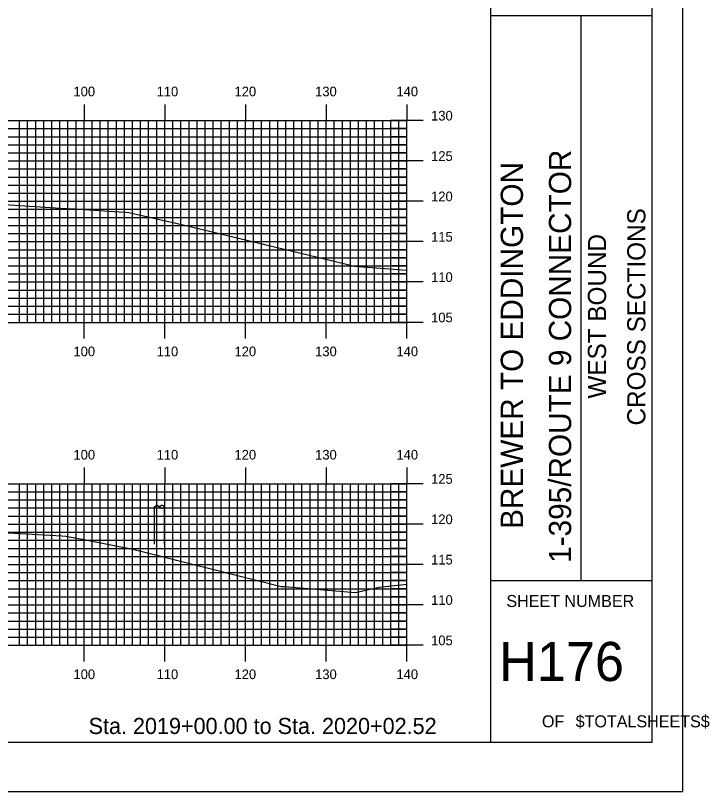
# Model space of a CAD drawing. Extents: x 855468 to 855811, y 366605 to 366825.
# Drawn here: x 855725.1 to 855811.1, y 366604.9 to 366701.1 of the extents above; entities that cross this region are included whole.
import ezdxf

# ---------------------------------------------------------------- set-up
doc = ezdxf.new("R2010")
doc.units = 0
for name, color, linetype in [('BORDER', 7, 'Continuous'), ('H_V ANNOTATION', 7, 'Continuous'), ('MAJOR', 7, 'Continuous'), ('MINOR', 7, 'Continuous'), ('PLOT BOUNDARY', 7, 'Continuous'), ('S_Roadway_Centerline', 7, 'Continuous'), ('S_Utilities_Pole_StreetLight', 7, 'Continuous')]:
    doc.layers.add(name, color=color, linetype=linetype)

msp = doc.modelspace()

# ---------------------------------------------------------------- linework, layer by layer
at = {"layer": 'BORDER'}
for p, q in [((855783.982, 366611.055), (855783.982, 366821.055)), ((855783.982, 366701.061), (855803.982, 366701.061)), ((855795.164, 366631.061), (855795.164, 366701.061)), ((855783.982, 366631.061), (855803.982, 366631.061))]:
    msp.add_line(p, q, dxfattribs=at)
msp.add_lwpolyline([(855483.982, 366611.055), (855803.982, 366611.055), (855803.982, 366821.055), (855483.982, 366821.055)], close=True, dxfattribs=at)
at = {"layer": 'MAJOR'}
for p, q in [((855733.582, 366690.059), (855733.582, 366688.055)), ((855743.582, 366690.059), (855743.582, 366688.055)), ((855753.582, 366690.059), (855753.582, 366688.055)), ((855763.582, 366690.059), (855763.582, 366688.055)), ((855773.582, 366690.059), (855773.582, 366688.055)), ((855493.582, 366688.055), (855773.582, 366688.055)), ((855493.582, 366688.055), (855773.582, 366688.055)), ((855733.582, 366663.055), (855733.582, 366688.055)), ((855743.582, 366663.055), (855743.582, 366688.055)), ((855753.582, 366663.055), (855753.582, 366688.055)), ((855763.582, 366663.055), (855763.582, 366688.055)), ((855775.586, 366688.055), (855771.578, 366688.055)), ((855773.582, 366663.055), (855773.582, 366688.055)), ((855773.582, 366663.055), (855773.582, 366688.055)), ((855493.582, 366683.055), (855773.582, 366683.055)), ((855775.586, 366683.055), (855771.578, 366683.055)), ((855493.582, 366678.055), (855773.582, 366678.055)), ((855775.586, 366678.055), (855771.578, 366678.055)), ((855493.582, 366673.055), (855773.582, 366673.055)), ((855775.586, 366673.055), (855771.578, 366673.055)), ((855493.582, 366668.055), (855773.582, 366668.055)), ((855775.586, 366668.055), (855771.578, 366668.055)), ((855493.582, 366663.055), (855773.582, 366663.055)), ((855493.582, 366663.055), (855773.582, 366663.055)), ((855733.582, 366661.051), (855733.582, 366663.055)), ((855743.582, 366661.051), (855743.582, 366663.055)), ((855753.582, 366661.051), (855753.582, 366663.055)), ((855763.582, 366661.051), (855763.582, 366663.055)), ((855775.586, 366663.055), (855771.578, 366663.055)), ((855773.582, 366661.051), (855773.582, 366663.055)), ((855733.582, 366645.059), (855733.582, 366643.055)), ((855743.582, 366645.059), (855743.582, 366643.055)), ((855753.582, 366645.059), (855753.582, 366643.055)), ((855763.582, 366645.059), (855763.582, 366643.055)), ((855773.582, 366645.059), (855773.582, 366643.055)), ((855493.582, 366643.055), (855773.582, 366643.055)), ((855493.582, 366643.055), (855773.582, 366643.055)), ((855733.582, 366623.055), (855733.582, 366643.055)), ((855743.582, 366623.055), (855743.582, 366643.055)), ((855753.582, 366623.055), (855753.582, 366643.055)), ((855763.582, 366623.055), (855763.582, 366643.055)), ((855775.586, 366643.055), (855771.578, 366643.055)), ((855773.582, 366623.055), (855773.582, 366643.055)), ((855773.582, 366623.055), (855773.582, 366643.055)), ((855493.582, 366638.055), (855773.582, 366638.055)), ((855775.586, 366638.055), (855771.578, 366638.055)), ((855493.582, 366633.055), (855773.582, 366633.055)), ((855775.586, 366633.055), (855771.578, 366633.055)), ((855493.582, 366628.055), (855773.582, 366628.055)), ((855775.586, 366628.055), (855771.578, 366628.055)), ((855493.582, 366623.055), (855773.582, 366623.055)), ((855493.582, 366623.055), (855773.582, 366623.055)), ((855733.582, 366621.051), (855733.582, 366623.055)), ((855743.582, 366621.051), (855743.582, 366623.055)), ((855753.582, 366621.051), (855753.582, 366623.055)), ((855763.582, 366621.051), (855763.582, 366623.055)), ((855775.586, 366623.055), (855771.578, 366623.055)), ((855773.582, 366621.051), (855773.582, 366623.055))]:
    msp.add_line(p, q, dxfattribs=at)
at = {"layer": 'MINOR'}
for p, q in [((855725.582, 366663.055), (855725.582, 366688.055)), ((855726.582, 366663.055), (855726.582, 366688.055)), ((855727.582, 366663.055), (855727.582, 366688.055)), ((855728.582, 366663.055), (855728.582, 366688.055)), ((855729.582, 366663.055), (855729.582, 366688.055)), ((855730.582, 366663.055), (855730.582, 366688.055)), ((855731.582, 366663.055), (855731.582, 366688.055)), ((855732.582, 366663.055), (855732.582, 366688.055)), ((855734.582, 366663.055), (855734.582, 366688.055)), ((855735.582, 366663.055), (855735.582, 366688.055)), ((855736.582, 366663.055), (855736.582, 366688.055)), ((855737.582, 366663.055), (855737.582, 366688.055)), ((855738.582, 366663.055), (855738.582, 366688.055)), ((855739.582, 366663.055), (855739.582, 366688.055)), ((855740.582, 366663.055), (855740.582, 366688.055)), ((855741.582, 366663.055), (855741.582, 366688.055)), ((855742.582, 366663.055), (855742.582, 366688.055)), ((855744.582, 366663.055), (855744.582, 366688.055)), ((855745.582, 366663.055), (855745.582, 366688.055)), ((855746.582, 366663.055), (855746.582, 366688.055)), ((855747.582, 366663.055), (855747.582, 366688.055)), ((855748.582, 366663.055), (855748.582, 366688.055)), ((855749.582, 366663.055), (855749.582, 366688.055)), ((855750.582, 366663.055), (855750.582, 366688.055)), ((855751.582, 366663.055), (855751.582, 366688.055)), ((855752.582, 366663.055), (855752.582, 366688.055)), ((855754.582, 366663.055), (855754.582, 366688.055)), ((855755.582, 366663.055), (855755.582, 366688.055)), ((855756.582, 366663.055), (855756.582, 366688.055)), ((855757.582, 366663.055), (855757.582, 366688.055)), ((855758.582, 366663.055), (855758.582, 366688.055)), ((855759.582, 366663.055), (855759.582, 366688.055)), ((855760.582, 366663.055), (855760.582, 366688.055)), ((855761.582, 366663.055), (855761.582, 366688.055)), ((855762.582, 366663.055), (855762.582, 366688.055)), ((855764.582, 366663.055), (855764.582, 366688.055)), ((855765.582, 366663.055), (855765.582, 366688.055)), ((855766.582, 366663.055), (855766.582, 366688.055)), ((855767.582, 366663.055), (855767.582, 366688.055)), ((855768.582, 366663.055), (855768.582, 366688.055)), ((855769.582, 366663.055), (855769.582, 366688.055)), ((855770.582, 366663.055), (855770.582, 366688.055)), ((855771.582, 366663.055), (855771.582, 366688.055)), ((855772.582, 366663.055), (855772.582, 366688.055)), ((855493.582, 366687.055), (855773.582, 366687.055)), ((855773.582, 366687.055), (855771.578, 366687.055)), ((855493.582, 366686.055), (855773.582, 366686.055)), ((855773.582, 366686.055), (855771.578, 366686.055)), ((855493.582, 366685.055), (855773.582, 366685.055)), ((855773.582, 366685.055), (855771.578, 366685.055)), ((855493.582, 366684.055), (855773.582, 366684.055)), ((855773.582, 366684.055), (855771.578, 366684.055)), ((855493.582, 366682.055), (855773.582, 366682.055)), ((855773.582, 366682.055), (855771.578, 366682.055)), ((855493.582, 366681.055), (855773.582, 366681.055)), ((855773.582, 366681.055), (855771.578, 366681.055)), ((855493.582, 366680.055), (855773.582, 366680.055)), ((855773.582, 366680.055), (855771.578, 366680.055)), ((855493.582, 366679.055), (855773.582, 366679.055)), ((855773.582, 366679.055), (855771.578, 366679.055)), ((855493.582, 366677.055), (855773.582, 366677.055)), ((855773.582, 366677.055), (855771.578, 366677.055)), ((855493.582, 366676.055), (855773.582, 366676.055)), ((855773.582, 366676.055), (855771.578, 366676.055)), ((855493.582, 366675.055), (855773.582, 366675.055)), ((855773.582, 366675.055), (855771.578, 366675.055)), ((855493.582, 366674.055), (855773.582, 366674.055)), ((855773.582, 366674.055), (855771.578, 366674.055)), ((855493.582, 366672.055), (855773.582, 366672.055)), ((855773.582, 366672.055), (855771.578, 366672.055)), ((855493.582, 366671.055), (855773.582, 366671.055)), ((855773.582, 366671.055), (855771.578, 366671.055)), ((855493.582, 366670.055), (855773.582, 366670.055)), ((855773.582, 366670.055), (855771.578, 366670.055)), ((855493.582, 366669.055), (855773.582, 366669.055)), ((855773.582, 366669.055), (855771.578, 366669.055)), ((855493.582, 366667.055), (855773.582, 366667.055)), ((855773.582, 366667.055), (855771.578, 366667.055)), ((855493.582, 366666.055), (855773.582, 366666.055)), ((855773.582, 366666.055), (855771.578, 366666.055)), ((855493.582, 366665.055), (855773.582, 366665.055)), ((855773.582, 366665.055), (855771.578, 366665.055)), ((855493.582, 366664.055), (855773.582, 366664.055)), ((855773.582, 366664.055), (855771.578, 366664.055)), ((855725.582, 366623.055), (855725.582, 366643.055)), ((855726.582, 366623.055), (855726.582, 366643.055)), ((855727.582, 366623.055), (855727.582, 366643.055)), ((855728.582, 366623.055), (855728.582, 366643.055)), ((855729.582, 366623.055), (855729.582, 366643.055)), ((855730.582, 366623.055), (855730.582, 366643.055)), ((855731.582, 366623.055), (855731.582, 366643.055)), ((855732.582, 366623.055), (855732.582, 366643.055)), ((855734.582, 366623.055), (855734.582, 366643.055)), ((855735.582, 366623.055), (855735.582, 366643.055)), ((855736.582, 366623.055), (855736.582, 366643.055)), ((855737.582, 366623.055), (855737.582, 366643.055)), ((855738.582, 366623.055), (855738.582, 366643.055)), ((855739.582, 366623.055), (855739.582, 366643.055)), ((855740.582, 366623.055), (855740.582, 366643.055)), ((855741.582, 366623.055), (855741.582, 366643.055)), ((855742.582, 366623.055), (855742.582, 366643.055)), ((855744.582, 366623.055), (855744.582, 366643.055)), ((855745.582, 366623.055), (855745.582, 366643.055)), ((855746.582, 366623.055), (855746.582, 366643.055)), ((855747.582, 366623.055), (855747.582, 366643.055)), ((855748.582, 366623.055), (855748.582, 366643.055)), ((855749.582, 366623.055), (855749.582, 366643.055)), ((855750.582, 366623.055), (855750.582, 366643.055)), ((855751.582, 366623.055), (855751.582, 366643.055)), ((855752.582, 366623.055), (855752.582, 366643.055)), ((855754.582, 366623.055), (855754.582, 366643.055)), ((855755.582, 366623.055), (855755.582, 366643.055)), ((855756.582, 366623.055), (855756.582, 366643.055)), ((855757.582, 366623.055), (855757.582, 366643.055)), ((855758.582, 366623.055), (855758.582, 366643.055)), ((855759.582, 366623.055), (855759.582, 366643.055)), ((855760.582, 366623.055), (855760.582, 366643.055)), ((855761.582, 366623.055), (855761.582, 366643.055)), ((855762.582, 366623.055), (855762.582, 366643.055)), ((855764.582, 366623.055), (855764.582, 366643.055)), ((855765.582, 366623.055), (855765.582, 366643.055)), ((855766.582, 366623.055), (855766.582, 366643.055)), ((855767.582, 366623.055), (855767.582, 366643.055)), ((855768.582, 366623.055), (855768.582, 366643.055)), ((855769.582, 366623.055), (855769.582, 366643.055)), ((855770.582, 366623.055), (855770.582, 366643.055)), ((855771.582, 366623.055), (855771.582, 366643.055)), ((855772.582, 366623.055), (855772.582, 366643.055)), ((855493.582, 366642.055), (855773.582, 366642.055)), ((855773.582, 366642.055), (855771.578, 366642.055)), ((855493.582, 366641.055), (855773.582, 366641.055)), ((855773.582, 366641.055), (855771.578, 366641.055)), ((855493.582, 366640.055), (855773.582, 366640.055)), ((855773.582, 366640.055), (855771.578, 366640.055)), ((855493.582, 366639.055), (855773.582, 366639.055)), ((855773.582, 366639.055), (855771.578, 366639.055)), ((855493.582, 366637.055), (855773.582, 366637.055)), ((855773.582, 366637.055), (855771.578, 366637.055)), ((855493.582, 366636.055), (855773.582, 366636.055)), ((855773.582, 366636.055), (855771.578, 366636.055)), ((855493.582, 366635.055), (855773.582, 366635.055)), ((855773.582, 366635.055), (855771.578, 366635.055)), ((855493.582, 366634.055), (855773.582, 366634.055)), ((855773.582, 366634.055), (855771.578, 366634.055)), ((855493.582, 366632.055), (855773.582, 366632.055)), ((855773.582, 366632.055), (855771.578, 366632.055)), ((855493.582, 366631.055), (855773.582, 366631.055)), ((855773.582, 366631.055), (855771.578, 366631.055)), ((855493.582, 366630.055), (855773.582, 366630.055)), ((855773.582, 366630.055), (855771.578, 366630.055)), ((855493.582, 366629.055), (855773.582, 366629.055)), ((855773.582, 366629.055), (855771.578, 366629.055)), ((855493.582, 366627.055), (855773.582, 366627.055)), ((855773.582, 366627.055), (855771.578, 366627.055)), ((855493.582, 366626.055), (855773.582, 366626.055)), ((855773.582, 366626.055), (855771.578, 366626.055)), ((855493.582, 366625.055), (855773.582, 366625.055)), ((855773.582, 366625.055), (855771.578, 366625.055)), ((855493.582, 366624.055), (855773.582, 366624.055)), ((855773.582, 366624.055), (855771.578, 366624.055))]:
    msp.add_line(p, q, dxfattribs=at)
at = {"layer": 'PLOT BOUNDARY'}
msp.add_lwpolyline([(855467.796, 366604.937), (855807.796, 366604.937), (855807.796, 366824.937), (855467.796, 366824.937)], close=True, dxfattribs=at)
at = {"layer": 'S_Roadway_Centerline'}
for points in [[(855723.706, 366677.657), (855730.643, 366677.215), (855732.433, 366677.101), (855739.144, 366676.679), (855745.851, 366675.147), (855756.145, 366672.657), (855764.581, 366670.652), (855767.084, 366670.023), (855773.582, 366669.525)], [(855724.168, 366636.967), (855730.829, 366636.613), (855731.3, 366636.583), (855733.534, 366636.139), (855739.617, 366634.963), (855754.723, 366631.14), (855758.013, 366630.332), (855758.398, 366630.326), (855767.211, 366629.579), (855770.165, 366630.236), (855773.582, 366630.615)]]:
    msp.add_lwpolyline(points, dxfattribs=at)
at = {"layer": 'S_Utilities_Pole_StreetLight'}
for p, q in [((855742.296, 366635.581), (855742.293, 366640.2)), ((855742.296, 366640.2), (855742.452, 366640.311)), ((855742.765, 366640.311), (855742.921, 366640.2)), ((855743.078, 366640.311), (855742.921, 366640.2)), ((855742.921, 366640.2), (855743.078, 366640.09)), ((855743.546, 366640.2), (855743.39, 366640.311)), ((855743.39, 366640.09), (855743.546, 366640.2)), ((855743.546, 366635.581), (855743.543, 366640.2))]:
    msp.add_line(p, q, dxfattribs=at)
for centre, start, end in [((855742.609, 366640.09), 90, 125.26439), ((855742.609, 366640.09), 54.73561, 90), ((855743.234, 366640.09), 90, 125.26439), ((855743.234, 366640.311), 234.73561, 270), ((855743.234, 366640.09), 54.73561, 90), ((855743.234, 366640.311), 270, 305.26439)]:
    msp.add_arc(centre, 0.271, start, end, dxfattribs=at)

# ---------------------------------------------------------------- texts
at = {"layer": 'BORDER'}
for s, height, p in [('1-395/ROUTE 9 CONNECTOR', 2.75575, (855793.937, 366633.255)), ('BREWER TO EDDINGTON', 2.75575, (855787.966, 366637.464)), ('CROSS SECTIONS', 2.25, (855803.136, 366650.277)), ('WEST BOUND', 2.25, (855798.261, 366653.608))]:
    msp.add_text(s, height=height, rotation=90, dxfattribs=at).set_placement(p)
for s, height, p in [('SHEET NUMBER', 1.49054, (855785.913, 366627.788)), ('H176', 4.8388, (855785.013, 366618.62)), ('OF', 1.4905, (855790.316, 366612.881)), ('$TOTALSHEETS$', 1.49054, (855794.495, 366612.881))]:
    msp.add_text(s, height=height, dxfattribs=at).set_placement(p)
at = {"layer": 'H_V ANNOTATION'}
for s, height, p in [('100', 1.2, (855732.266, 366691.055)), ('110', 1.2, (855742.566, 366691.055)), ('120', 1.2, (855752.223, 366691.055)), ('130', 1.2, (855762.212, 366691.055)), ('140', 1.2, (855772.287, 366691.055)), ('130', 1.2, (855776.582, 366688.055)), ('125', 1.2, (855776.582, 366683.055)), ('120', 1.2, (855776.582, 366678.055)), ('115', 1.2, (855776.582, 366673.055)), ('110', 1.2, (855776.582, 366668.055)), ('105', 1.2, (855776.582, 366663.055)), ('100', 1.2, (855732.266, 366658.855)), ('110', 1.2, (855742.566, 366658.855)), ('120', 1.2, (855752.223, 366658.855)), ('130', 1.2, (855762.212, 366658.855)), ('140', 1.2, (855772.287, 366658.855)), ('100', 1.2, (855732.266, 366646.055)), ('110', 1.2, (855742.566, 366646.055)), ('120', 1.2, (855752.223, 366646.055)), ('130', 1.2, (855762.212, 366646.055)), ('140', 1.2, (855772.287, 366646.055)), ('125', 1.2, (855776.582, 366643.055)), ('120', 1.2, (855776.582, 366638.055)), ('115', 1.2, (855776.582, 366633.055)), ('110', 1.2, (855776.582, 366628.055)), ('105', 1.2, (855776.582, 366623.055)), ('100', 1.2, (855732.266, 366618.855)), ('110', 1.2, (855742.566, 366618.855)), ('120', 1.2, (855752.223, 366618.855)), ('130', 1.2, (855762.212, 366618.855)), ('140', 1.2, (855772.287, 366618.855)), ('Sta. 2019+00.00 to Sta. 2020+02.52', 2.0004, (855734.135, 366612.055))]:
    msp.add_text(s, height=height, dxfattribs=at).set_placement(p)

doc.saveas('drawing.dxf')
